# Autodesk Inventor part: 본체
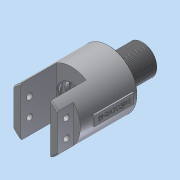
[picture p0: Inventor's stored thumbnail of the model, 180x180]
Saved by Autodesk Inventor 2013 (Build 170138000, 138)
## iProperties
Created: 2019-02
Part Number: 본체
Material: 알루미늄 6061
Document SubType Name: Modeling
Designer: Administrator
Density: 2.71 g/cm^3
Mass: 347.114 g
Surface Area: 290.212 cm^2
Volume: 128.086 cm^3
Author: Administrator
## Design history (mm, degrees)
sketch "스케치1"
  geometry: C1 r 29 at (0, 0); 1 further point
  constraints: 1 centre point, 1 coincident
  dimensions: "d0" = 58 diameter of C1
extrude "돌출1" new body sketch "스케치1" distance "d3" = 74; taper "d4" = 0 deg
sketch "스케치2"
  geometry: L1 (-15, 24.819)-(-15, -24.819); L2 (15, 24.819)-(15, -24.819); A1 r 29 centre (0, 0) between (-15, 24.819) and (-15, -24.819) reference; A2 r 29 centre (0, 0) between (-15, 24.819) and (-15, -24.819) reference
  constraints: 8 point on circle, 4 end point, 2 vertical, 1 parallel
  dimensions: "d5" = 30 distance between parallel lines of L2 L1
extrude "돌출2" cut sketch "스케치2" distance "d6" = 36; taper "d7" = 0 deg
sketch "스케치3"
  geometry: L1 (22, 18.894)-(22, -18.894); A1 r 29 centre (0, 0) between (15, -24.819) and (15, 24.819) reference
  constraints: 2 end point, 2 point on circle, 1 vertical
  dimensions: "d8" = 22 distance from line of L1 A1.centre
extrude "돌출3" cut sketch "스케치3" distance "d9" = 16; taper "d10" = 0 deg
sketch "스케치4"
  geometry: C1 r 29 at (0, 0) reference; C2 r 13 at (0, 0)
  constraints: 1 centre point, 1 coincident
  dimensions: "d11" = 26 diameter of C2
extrude "돌출4" join sketch "스케치4" distance "d14" = 5; taper "d15" = 0 deg
sketch "스케치5"
  geometry: C1 r 13 at (0, 0) reference; C2 r 15 at (0, 0)
  constraints: 1 centre point, 1 coincident
  dimensions: "d16" = 30 diameter of C2
extrude "돌출5" join sketch "스케치5" distance "d18" = 29; taper "d19" = 0 deg
sketch "스케치6"
  geometry: 1 further point
sketch "스케치7"
  geometry: L1 (18.894, 58)-(18.894, 74) reference; L2 (24.819, 74)-(18.894, 74) reference; L3 (24.819, 74)-(24.819, 38) reference; L4 (24.819, 38)-(24.819, 38) reference; L5 (24.819, 38)-(24.819, 74) reference; L6 (18.894, 74)-(24.819, 74) reference; L7 (18.894, 74)-(18.894, 58) reference; L8 (18.894, 58)-(-18.894, 58) reference; L9 (-18.894, 58)-(-18.894, 74) reference; L10 (-24.819, 74)-(-18.894, 74) reference; L11 (-24.819, 74)-(-24.819, 38) reference; L12 (-24.819, 38)-(-24.819, 38) reference; L13 (-24.819, 38)-(-24.819, 74) reference; L14 (-18.894, 74)-(-24.819, 74) reference; L15 (-18.894, 74)-(-18.894, 58) reference; L16 (-18.894, 58)-(18.894, 58) reference; L17 (-29, 0)-(29, 0) reference; L18 (-15, -34)-(15, -34) reference; L19 (15, -5)-(-15, -5) reference; L20 (-13, -5)-(13, -5) reference; L21 (13, 0)-(-13, 0) reference; L22 (0, 38)-(0, -34); L23 (-24.819, 38)-(24.819, 38) reference; L24 (14, 38)-(14, 35.35); L25 (14, 35.35)-(17, 35.35); L26 (17, 35.35)-(17, 30.65); L27 (17, 30.65)-(14, 30.65); L28 (14, 26.35)-(17, 26.35); L29 (17, 26.35)-(17, 21.65); L30 (17, 21.65)-(14, 21.65); L31 (14, 21.65)-(14, 18); L32 (14, 18)-(16, 18); L33 (16, 18)-(16, 11); L34 (16, 11)-(4, 11); L35 (4, 11)-(4, -12); L36 (4, -12)-(0, -12); L37 (14, 30.65)-(14, 26.35); 5 further points
  constraints: 30 end point, 9 parallel, 6 midpoint, 4 collinear, 4 point on line, 3 perpendicular, 1 vertical alignment
  dimensions: "d20" = 20 distance from line of L23 L32.end; "d21" = 28 diameter of L24 L22; "d22" = 34 diameter of L26 L22; "d23" = 4.7 distance of L25.end L26.end; "d24" = 9 distance of L29.end L26.end; "d25" = 7.35 distance from line of L26.end L23; "d26" = 7 distance of L32.end L33.end; "d27" = 32 diameter of L33 L22; "d28" = 8 diameter of L35 L22; "d30" = 22 distance between parallel lines of L18 L36
revolve "회전1" sketch "스케치7" stored, may be unused: angle "d31" = 90 deg
sketch "스케치8"
  geometry: C1 r 15 at (0, 0) reference; 1 further point
  constraints: 1 coincident
sketch "스케치9"
  geometry: L1 (0, 37.789)-(0, 0) reference; L2 (-16, 37.789)-(0, 37.789) reference; L3 (0, 43.714)-(0, 37.789) reference; L4 (0, 43.714)-(-36, 43.714) reference; L5 (-36, 43.714)-(-36, 43.714) reference; L6 (-36, 43.714)-(0, 43.714) reference; L7 (0, 37.789)-(0, 43.714) reference; L8 (0, 37.789)-(-16, 37.789) reference; L9 (-16, 37.789)-(-16, 0) reference; L10 (-16, 0)-(0, 0) reference; L11 (0, -5.925)-(0, 0) reference; L12 (0, -5.925)-(-36, -5.925) reference; L13 (-36, -5.925)-(-36, -5.925) reference; L14 (-36, -5.925)-(0, -5.925) reference; L15 (0, 0)-(0, -5.925) reference; L16 (0, 0)-(-16, 0) reference; L17 (-16, 0)-(-16, 37.789) reference; L18 (-74, 47.894)-(-74, -10.106) reference; L19 (-108, 33.894)-(-108, 3.894) reference; L20 (-79, 3.894)-(-79, 33.894) reference; L21 (-79, 31.894)-(-79, 5.894) reference; L22 (-74, 5.894)-(-74, 31.894) reference; L23 (-16, 37.789)-(-16, 0) reference; L24 (-63, 2.894)-(-63, 34.894) reference; L25 (-74, 47.894)-(-74, -10.106) reference; L26 (-74, 47.894)-(-36, 47.894) reference; L27 (-74, -10.106)-(-36, -10.106) reference; C1 r 3 at (-9, 27.894); C2 r 3 at (-9, 9.894); 1 further point
  constraints: 2 centre point, 1 equal radius, 1 vertical alignment
  dimensions: "d32" = 18 distance of C2.centre C1.centre; "d34" = 9 distance from line of C1.centre L1; "d35" = 20 vertical distance of C1.centre L26.end; "d36" = 6 diameter of C1
extrude "돌출6" cut sketch "스케치9" distance "d37" = 10; taper "d38" = 0 deg
node "작업 평면1"
sketch "스케치10"
  geometry: L1 (-5, 45)-(5, 45); L2 (5, 45)-(5, 5); L3 (5, 5)-(-5, 5); L4 (-5, 5)-(-5, 45); L5 (-5, 45)-(5, 5); L6 (5, 45)-(-5, 5); L7 (-29, 0)-(29, 0) reference; 3 further points
  constraints: 12 end point, 3 midpoint, 2 parallel, 1 horizontal, 1 perpendicular, 1 vertical alignment
  dimensions: "d40" = 40 distance of L1.end L2.end; "d42" = 10 distance of L1.start L1.end; "d43" = 5 distance between parallel lines of L3 L7
extrude "돌출7" join sketch "스케치10" stored distance "d44" = 1; taper "d45" = 0 deg
sketch "스케치11"
  geometry: L1 (45, 5)-(45, -5) reference; 2 further points
  constraints: 1 horizontal alignment, 1 other
  dimensions: "d46" = 20 distance from line of L1 point (25, 0)
feature "엠보싱1" sketch "스케치11" dims "d47" = 0.5, "d48" = 0
node "스케치12"
hole "구멍1" sketch "스케치8" diameter "d49" = 12.376; stored, may be unused: countersink angle "d53" = 90 deg, drill point angle "d55" = 118 deg; dims "d50" = 18, "d51" = 4, "d52" = 2, "d54" = 22
fillet "모깎기1" dims "d56" = 0.8
chamfer "모따기1" distance "d57" = 1; stored, may be unused: second distance "d58" = 2, angle "d59" = 45 deg
chamfer "모따기2" distance "d60" = 1; stored, may be unused: second distance "d61" = 2, angle "d62" = 45 deg
feature "스레드3" dims "d67" = 10, "d68" = 0
node "솔리드1"
mirror "대칭1"
mirror "대칭2"
node "투영된 루프1"
node "투영된 루프2"
node "투영된 루프3"
node "투영된 루프4"
node "투영된 루프5"
node "투영된 루프6"
node "투영된 루프7"
